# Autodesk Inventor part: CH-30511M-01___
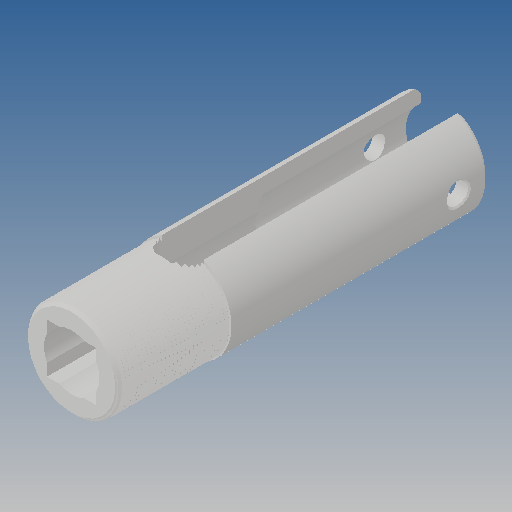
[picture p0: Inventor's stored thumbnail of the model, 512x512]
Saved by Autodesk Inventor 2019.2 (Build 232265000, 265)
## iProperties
Created: 2010-06
Part Number: CH-30511M-01___
Material: Ogólny
Document SubType Name: Modeling
Designer: CADENGINEERING4
Density: 1 g/cm^3
Appearance: Domyślna
Author: CADENGINEERING4
Revision Number: ANY
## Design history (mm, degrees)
feature "NONE"
node "Bryła1"
